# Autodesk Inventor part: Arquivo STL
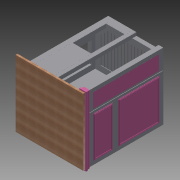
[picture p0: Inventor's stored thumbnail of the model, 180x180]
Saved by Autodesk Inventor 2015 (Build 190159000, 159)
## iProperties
Created: 2015-04
Part Number: Arquivo STL
Material: Generic
Document SubType Name: Modeling
Designer: suporte
Density: 1 g/cm^3
Appearance: Default
Author: suporte
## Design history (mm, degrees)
derived "Drywall.iam"
body "Solid1"
node "Base.ipt:1"
node "Moldura 1.ipt:1"
body "Solid2"
node "Moldura 2.ipt:1"
body "Solid3"
node "Rodapé.ipt:1"
body "Solid4"
node "Frame0001.iam:1::Kevin  00000006:1"
body "Solid5"
node "Frame0001.iam:1::Kevin  00000062:1"
body "Solid6"
node "Canto Madeira.ipt:1"
body "Solid7"
node "Canto Madeira 2.ipt:1"
body "Solid8"
node "Placa 1.ipt:1"
body "Solid9"
node "Placa 2.ipt:1"
body "Solid10"
node "Placa 1.ipt:2"
body "Solid11"
node "Placa 3.ipt:1"
body "Solid12"
node "Placa 3.ipt:2"
body "Solid13"
node "Placa 4.ipt:1"
body "Solid14"
node "Placa 5.ipt:1"
body "Solid15"
node "Placa 6.ipt:1"
body "Solid16"
node "Placa 6.ipt:2"
body "Solid17"
node "Placa 7.ipt:1"
body "Solid18"
node "Placa 8.ipt:1"
body "Solid19"
node "Placa 8.ipt:2"
body "Solid20"
node "Placa 9.ipt:1"
body "Solid21"
node "Placa 11.ipt:1"
body "Solid22"
node "Placa 12.ipt:1"
body "Solid23"
node "Placa 13.ipt:1"
body "Solid24"
node "Placa 14.ipt:1"
body "Solid25"
node "Placa 15.ipt:1"
body "Solid26"
node "Placa 16.ipt:1"
body "Solid27"
node "Placa 18.ipt:1"
body "Solid28"
node "Placa 19.ipt:1"
body "Solid29"
node "Placa 16.ipt:2"
body "Solid30"
node "Placa 19.ipt:2"
body "Solid31"
node "Placa 20.ipt:1"
body "Solid32"
node "Placa 21.ipt:1"
body "Solid33"
node "Placa 22.ipt:1"
body "Solid34"
node "Placa 23.ipt:1"
body "Solid35"
node "Placa 24.ipt:1"
body "Solid36"
node "Placa 25.ipt:1"
body "Solid37"
node "Placa 26.ipt:1"
body "Solid38"
node "Placa 27.ipt:1"
body "Solid39"
node "Placa 27.ipt:2"
body "Solid40"
node "Placa Lã 1.ipt:1"
body "Solid41"
node "Placa 30.ipt:1"
body "Solid42"
node "Placa 32.ipt:1"
body "Solid43"
node "Placa 33.ipt:1"
body "Solid44"
node "Placa 34.ipt:1"
body "Solid45"
node "Placa 30.ipt:2"
body "Solid46"
node "Placa 34.ipt:2"
body "Solid47"
node "Placa 33.ipt:2"
body "Solid48"
node "Placa 35.ipt:1"
body "Solid49"
node "Placa 36.ipt:1"
body "Solid50"
node "Detalhe Pintado.ipt:1"
body "Solid51"
node "Placa Teto.ipt:1"
body "Solid52"
node "Placa 37.ipt:1"
body "Solid53"
node "Placa 38.ipt:1"
body "Solid54"
node "Placa 39.ipt:1"
body "Solid55"
node "Placa 40.ipt:1"
body "Solid56"
node "Placa 42.ipt:1"
body "Solid57"
node "Placa 44.ipt:1"
body "Solid58"
node "Placa 45.ipt:1"
body "Solid59"
node "Placa 46.ipt:1"
body "Solid60"
node "Placa 47.ipt:1"
body "Solid61"
node "Placa 48.ipt:1"
body "Solid62"
node "Placa 49.ipt:1"
body "Solid63"
node "Placa 50.ipt:1"
body "Solid64"
node "Placa 51.ipt:1"
body "Solid65"
node "placa 52.ipt:1"
body "Solid66"
node "placa 53.ipt:1"
body "Solid67"
node "Placa 54.ipt:1"
body "Solid68"
node "Placa 55.ipt:1"
body "Solid69"
node "placa 53.ipt:2"
body "Solid70"
node "placa 53.ipt:3"
body "Solid71"
node "placa 53.ipt:4"
body "Solid72"
node "Placa 54.ipt:2"
body "Solid73"
node "Placa 55.ipt:2"
body "Solid74"
